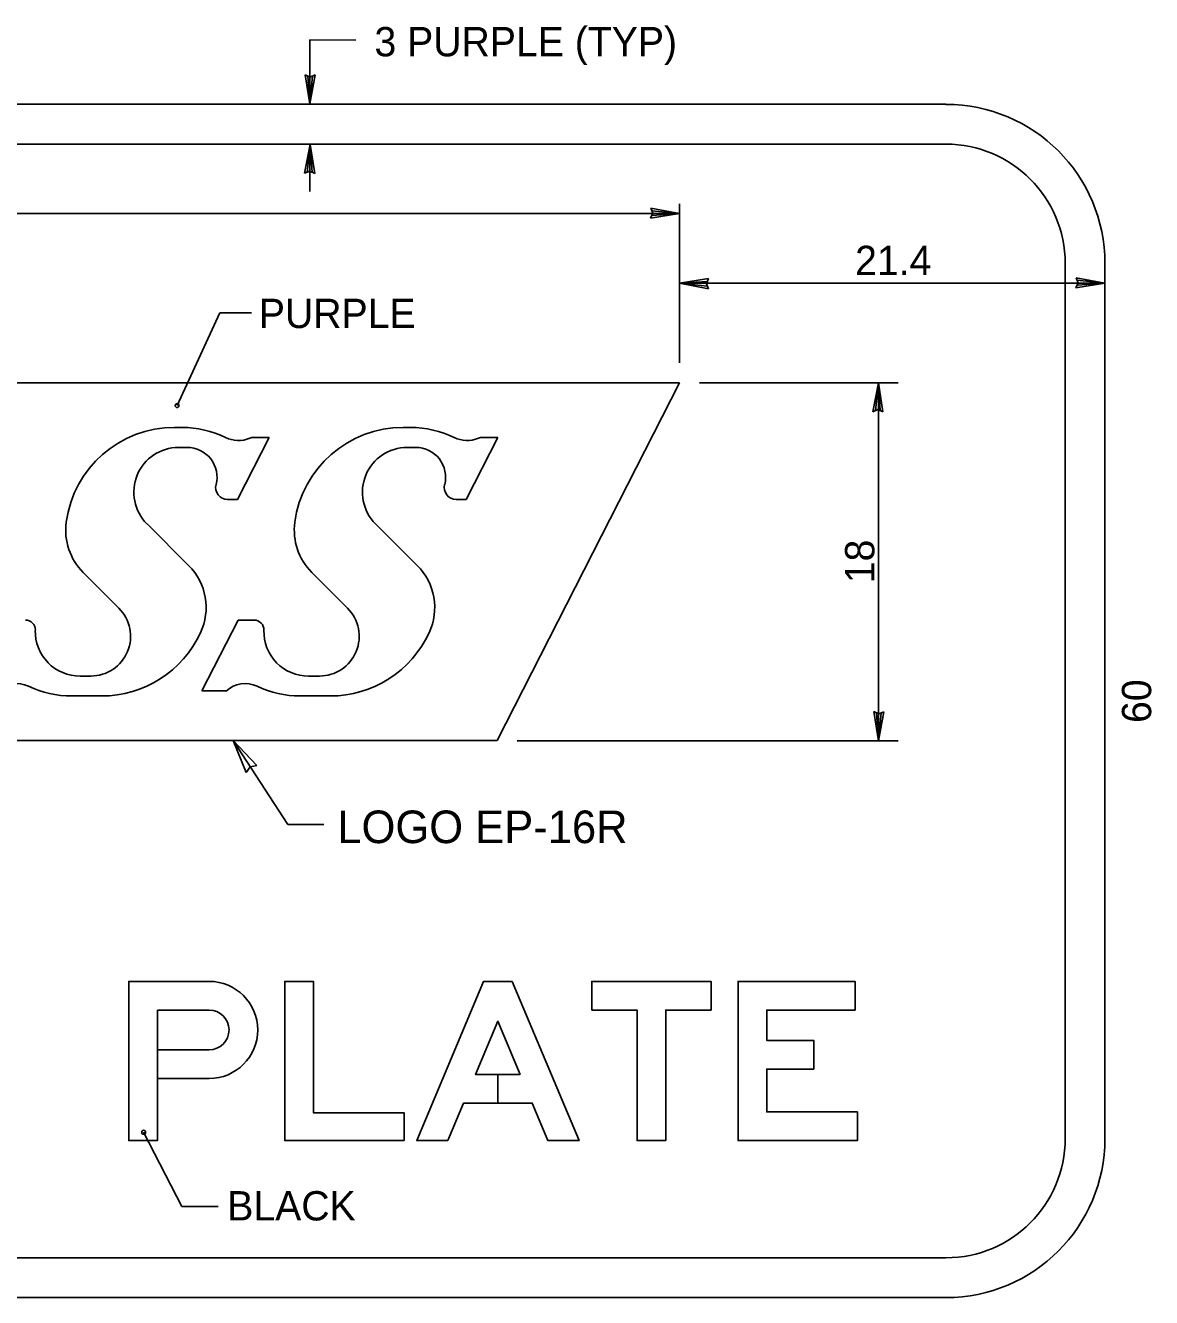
# Model space of a CAD drawing. Extents: x 60712 to 61344, y 9358 to 10016.
# Drawn here: x 60912.9 to 61020.6, y 9646 to 9767.5 of the extents above; entities that cross this region are included whole.
import ezdxf

# ---------------------------------------------------------------- set-up
doc = ezdxf.new("R2010")
doc.units = 0
for name, color, linetype in [('1', 7, 'Continuous'), ('52', 7, 'Continuous'), ('GSBWFill', 7, 'Continuous'), ('SignPanel', 7, 'Continuous')]:
    doc.layers.add(name, color=color, linetype=linetype)

msp = doc.modelspace()

# ---------------------------------------------------------------- linework, layer by layer
at = {"layer": '1'}
for p, q in [((60940.1, 9766.12), (60944.51, 9766.09)), ((60940.1, 9759.93), (60940.1, 9766.12)), ((60940.1, 9751.64), (60940.1, 9756.16)), ((60975.44, 9735.26), (60975.44, 9750.46)), ((60892.98, 9749.51), (60975.44, 9749.51)), ((60975.44, 9742.86), (61016.1, 9742.86)), ((60931.51, 9740.02), (60927.42, 9731.18)), ((60934.53, 9740.02), (60931.51, 9740.02)), ((60977.34, 9733.35), (60996.34, 9733.35)), ((60994.44, 9699.15), (60994.44, 9733.35)), ((60932.76, 9699.16), (60938, 9691.16)), ((60959.92, 9699.15), (60996.34, 9699.15)), ((60938, 9691.16), (60941.44, 9691.16)), ((60927.88, 9654.66), (60924.22, 9661.74)), ((60931.35, 9654.66), (60927.88, 9654.66))]:
    msp.add_line(p, q, dxfattribs=at)
for centre in [(60927.42, 9731.18), (60924.22, 9661.74)]:
    msp.add_circle(centre, 0.19, dxfattribs=at)
at = {"layer": '52'}
for p, q in [((60940.09, 9760), (60939.65, 9762.78)), ((60940.13, 9762.56), (60939.65, 9762.78)), ((60940.09, 9760), (60939.9, 9762.66)), ((60940.09, 9760), (60940.62, 9762.76)), ((60940.09, 9760), (60940.36, 9762.66)), ((60940.62, 9762.76), (60940.13, 9762.56)), ((60940.14, 9756.13), (60939.6, 9753.37)), ((60940.14, 9756.13), (60939.86, 9753.48)), ((60940.14, 9756.13), (60940.58, 9753.35)), ((60940.14, 9756.13), (60940.32, 9753.47)), ((60939.6, 9753.37), (60940.09, 9753.57)), ((60940.09, 9753.57), (60940.58, 9753.35)), ((60975.44, 9749.51), (60972.68, 9750.04)), ((60972.68, 9750.04), (60972.88, 9749.55)), ((60975.44, 9749.51), (60972.79, 9749.79)), ((60972.88, 9749.55), (60972.66, 9749.07)), ((60975.44, 9749.51), (60972.66, 9749.07)), ((60975.44, 9749.51), (60972.78, 9749.32)), ((60975.44, 9742.86), (60978.22, 9743.3)), ((60975.44, 9742.86), (60978.1, 9743.04)), ((60975.44, 9742.86), (60978.2, 9742.32)), ((60975.44, 9742.86), (60978.09, 9742.58)), ((60978, 9742.81), (60978.22, 9743.3)), ((60978.2, 9742.32), (60978, 9742.81)), ((61013.54, 9742.9), (61013.32, 9742.42)), ((61016.1, 9742.86), (61013.32, 9742.42)), ((61016.1, 9742.86), (61013.34, 9743.39)), ((61013.34, 9743.39), (61013.54, 9742.9)), ((61016.1, 9742.86), (61013.44, 9742.67)), ((61016.1, 9742.86), (61013.45, 9743.14)), ((60994.44, 9733.35), (60993.9, 9730.59)), ((60994.44, 9733.35), (60994.16, 9730.7)), ((60994.44, 9733.35), (60994.88, 9730.58)), ((60994.44, 9733.35), (60994.63, 9730.69)), ((60993.9, 9730.59), (60994.4, 9730.8)), ((60994.4, 9730.8), (60994.88, 9730.58)), ((60994.44, 9699.15), (60994, 9701.93)), ((60994.48, 9701.71), (60994, 9701.93)), ((60994.44, 9699.15), (60994.25, 9701.81)), ((60994.44, 9699.15), (60994.98, 9701.91)), ((60994.44, 9699.15), (60994.72, 9701.81)), ((60994.98, 9701.91), (60994.48, 9701.71)), ((60932.76, 9699.16), (60934.01, 9696.12)), ((60935.03, 9696.79), (60932.76, 9699.16)), ((60934.01, 9696.12), (60934.39, 9696.67)), ((60934.39, 9696.67), (60935.03, 9696.79))]:
    msp.add_line(p, q, dxfattribs=at)
at = {"layer": 'GSBWFill'}
for p, q in [((60925.54, 9673.42), (60930.48, 9673.42)), ((60925.54, 9673.42), (60930.48, 9673.42)), ((60925.54, 9673.42), (60930.48, 9673.42)), ((60925.54, 9666.88), (60930.48, 9666.88))]:
    msp.add_line(p, q, dxfattribs=at)
for points in [[(60930.48, 9676.16), (60922.8, 9676.16), (60922.8, 9660.95), (60925.54, 9660.95), (60925.54, 9666.88)], [(60930.48, 9676.16), (60922.8, 9676.16), (60922.8, 9660.95), (60925.54, 9660.95), (60925.54, 9673.42)], [(60930.48, 9676.16), (60922.8, 9676.16), (60922.8, 9660.95), (60925.54, 9660.95), (60925.54, 9673.42)], [(60930.48, 9669.62), (60925.54, 9669.62), (60925.54, 9673.42)], [(60930.48, 9669.62), (60925.54, 9669.62), (60925.54, 9666.88), (60930.48, 9666.88)], [(60930.48, 9669.62), (60925.54, 9669.62), (60925.54, 9666.88), (60930.48, 9666.88)]]:
    msp.add_lwpolyline(points, dxfattribs=at)
for points in [[(60949.11, 9660.95), (60949.11, 9663.61), (60940.44, 9663.61), (60940.44, 9676.16), (60937.7, 9676.16), (60937.7, 9660.95)], [(60949.11, 9660.95), (60949.11, 9663.61), (60940.44, 9663.61), (60940.44, 9676.16), (60937.7, 9676.16), (60937.7, 9660.95)], [(60949.11, 9660.95), (60949.11, 9663.61), (60940.44, 9663.61), (60940.44, 9676.16), (60937.7, 9676.16), (60937.7, 9660.95)], [(60954.79, 9664.53), (60961.36, 9664.53), (60962.86, 9660.95), (60965.83, 9660.95), (60959.44, 9676.16), (60956.71, 9676.16), (60950.32, 9660.95), (60953.29, 9660.95)], [(60960.21, 9667.26), (60958.08, 9667.26), (60958.08, 9664.53), (60961.36, 9664.53), (60962.86, 9660.95), (60965.83, 9660.95), (60959.44, 9676.16), (60956.71, 9676.16), (60950.32, 9660.95), (60953.29, 9660.95), (60954.79, 9664.53), (60958.08, 9664.53), (60958.08, 9667.26), (60955.94, 9667.26), (60958.08, 9672.35)], [(60960.21, 9667.26), (60958.08, 9667.26), (60958.08, 9664.53), (60961.36, 9664.53), (60962.86, 9660.95), (60965.83, 9660.95), (60959.44, 9676.16), (60956.71, 9676.16), (60950.32, 9660.95), (60953.29, 9660.95), (60954.79, 9664.53), (60958.08, 9664.53), (60958.08, 9667.26), (60955.94, 9667.26), (60958.08, 9672.35)], [(60967.05, 9673.42), (60971.38, 9673.42), (60971.38, 9660.95), (60974.12, 9660.95), (60974.12, 9673.42), (60978.45, 9673.42), (60978.45, 9676.16), (60967.05, 9676.16)], [(60967.05, 9673.42), (60971.38, 9673.42), (60971.38, 9660.95), (60974.12, 9660.95), (60974.12, 9673.42), (60978.45, 9673.42), (60978.45, 9676.16), (60967.05, 9676.16)], [(60967.05, 9673.42), (60971.38, 9673.42), (60971.38, 9660.95), (60974.12, 9660.95), (60974.12, 9673.42), (60978.45, 9673.42), (60978.45, 9676.16), (60967.05, 9676.16)], [(60992.44, 9663.69), (60983.77, 9663.69), (60983.77, 9667.78), (60988.26, 9667.78), (60988.26, 9670.52), (60983.77, 9670.52), (60983.77, 9673.42), (60992.21, 9673.42), (60992.21, 9676.16), (60981.03, 9676.16), (60981.03, 9660.95), (60992.44, 9660.95)], [(60992.44, 9663.69), (60983.77, 9663.69), (60983.77, 9667.78), (60988.26, 9667.78), (60988.26, 9670.52), (60983.77, 9670.52), (60983.77, 9673.42), (60992.21, 9673.42), (60992.21, 9676.16), (60981.03, 9676.16), (60981.03, 9660.95), (60992.44, 9660.95)], [(60992.44, 9663.69), (60983.77, 9663.69), (60983.77, 9667.78), (60988.26, 9667.78), (60988.26, 9670.52), (60983.77, 9670.52), (60983.77, 9673.42), (60992.21, 9673.42), (60992.21, 9676.16), (60981.03, 9676.16), (60981.03, 9660.95), (60992.44, 9660.95)], [(60960.21, 9667.26), (60958.08, 9672.35), (60955.94, 9667.26)]]:
    msp.add_lwpolyline(points, close=True, dxfattribs=at)
for major_axis in [(0, 4.64), (0, 4.64), (0, 4.64), (0, 1.9), (0, 1.9), (0, 1.9)]:
    msp.add_ellipse((60930.48, 9671.52), major_axis=major_axis, ratio=0.999994, start_param=3.141593, end_param=6.283185, dxfattribs=at)
at = {"layer": 'SignPanel'}
for p, q in [((60757.7, 9759.96), (61000.9, 9759.96)), ((60757.7, 9756.16), (61000.9, 9756.16)), ((61012.3, 9661.16), (61012.3, 9744.76)), ((61016.1, 9661.16), (61016.1, 9744.76)), ((60867.05, 9733.36), (60975.44, 9733.36)), ((60958.02, 9699.16), (60975.44, 9733.36)), ((60927.17, 9729.08), (60927.89, 9729.08)), ((60949.03, 9729.08), (60949.75, 9729.08)), ((60936.21, 9728.13), (60933.19, 9722.21)), ((60934.79, 9728.13), (60936.21, 9728.13)), ((60958.06, 9728.13), (60955.04, 9722.21)), ((60956.64, 9728.13), (60958.06, 9728.13)), ((60928.38, 9727.18), (60927.56, 9727.18)), ((60950.23, 9727.18), (60949.41, 9727.18)), ((60933.19, 9722.21), (60932.24, 9722.21)), ((60955.04, 9722.21), (60954.09, 9722.21)), ((60924.54, 9719.88), (60928.52, 9715.9)), ((60946.39, 9719.88), (60950.37, 9715.9)), ((60921.85, 9711.82), (60918.44, 9715.24)), ((60943.71, 9711.82), (60940.29, 9715.24)), ((60929.79, 9703.91), (60933.24, 9710.68)), ((60933.24, 9710.68), (60934.77, 9710.68)), ((60918.14, 9705.33), (60919.17, 9705.33)), ((60939.99, 9705.33), (60941.02, 9705.33)), ((60932.1, 9703.91), (60929.79, 9703.91)), ((60920.19, 9703.43), (60917.33, 9703.43)), ((60942.04, 9703.43), (60939.18, 9703.43)), ((60864.53, 9699.16), (60958.02, 9699.16)), ((60757.7, 9649.76), (61000.9, 9649.76)), ((60757.7, 9645.96), (61000.9, 9645.96))]:
    msp.add_line(p, q, dxfattribs=at)
for centre, radius, start, end in [((61000.9, 9744.75), 15.2, 0, 90), ((61000.9, 9744.75), 11.4, 0, 90), ((60927.17, 9718.63), 10.45, 90, 172.3089), ((60927.89, 9719.58), 9.5, 64.0896, 90), ((60949.02, 9718.63), 10.45, 90, 172.3089), ((60949.74, 9719.58), 9.5, 64.0896, 90), ((60933.29, 9730.69), 2.85, 244.0896, 292.0347), ((60934.79, 9726.99), 1.14, 90, 112.0347), ((60955.14, 9730.69), 2.85, 244.0896, 292.0347), ((60956.64, 9726.99), 1.14, 90, 112.0347), ((60927.56, 9722.9), 4.28, 90, 225), ((60928.38, 9724.33), 2.85, 345.6915, 90), ((60949.41, 9722.9), 4.28, 90, 225), ((60950.23, 9724.33), 2.85, 345.6915, 90), ((60932.24, 9723.34), 1.14, 165.6915, 270), ((60954.09, 9723.34), 1.14, 165.6915, 270), ((60922.47, 9719.26), 5.7, 172.3089, 225), ((60944.32, 9719.26), 5.7, 172.3089, 225), ((60924.49, 9711.87), 5.7, 334.95, 45), ((60946.34, 9711.87), 5.7, 334.95, 45), ((60919.17, 9709.13), 3.8, 270, 45), ((60941.02, 9709.13), 3.8, 270, 45), ((60912.92, 9709.73), 0.95, 358.6664, 90), ((60918.14, 9709.6), 4.28, 178.6665, 270), ((60934.77, 9709.73), 0.95, 358.6664, 90), ((60939.99, 9709.6), 4.28, 178.6665, 270), ((60920.19, 9713.88), 10.45, 270, 334.95), ((60942.04, 9713.88), 10.45, 270, 334.95), ((60912.07, 9701.96), 2.66, 64.3795, 133.1892), ((60917.33, 9712.93), 9.5, 244.3795, 270), ((60933.92, 9701.96), 2.66, 64.3795, 133.1892), ((60939.18, 9712.93), 9.5, 244.3795, 270), ((61000.9, 9661.15), 15.2, 270, 360), ((61000.9, 9661.15), 11.4, 270, 0)]:
    msp.add_arc(centre, radius, start, end, dxfattribs=at)

# ---------------------------------------------------------------- texts
at = {"layer": '1'}
for s, height, p in [('3 PURPLE (TYP)', 2.8, (60946.28, 9764.54)), ('21.4', 2.8, (60992.22, 9743.64)), ('PURPLE', 2.8, (60935.23, 9738.58)), ('LOGO EP-16R', 3.1111, (60942.73, 9689.37)), ('BLACK', 2.8, (60932.21, 9653.32))]:
    msp.add_text(s, height=height, dxfattribs=at).set_placement(p)
for s, p in [('18', (60994.06, 9714.2)), ('60', (61020.52, 9700.85))]:
    msp.add_text(s, height=2.8, rotation=90, dxfattribs=at).set_placement(p)

doc.saveas('drawing.dxf')
